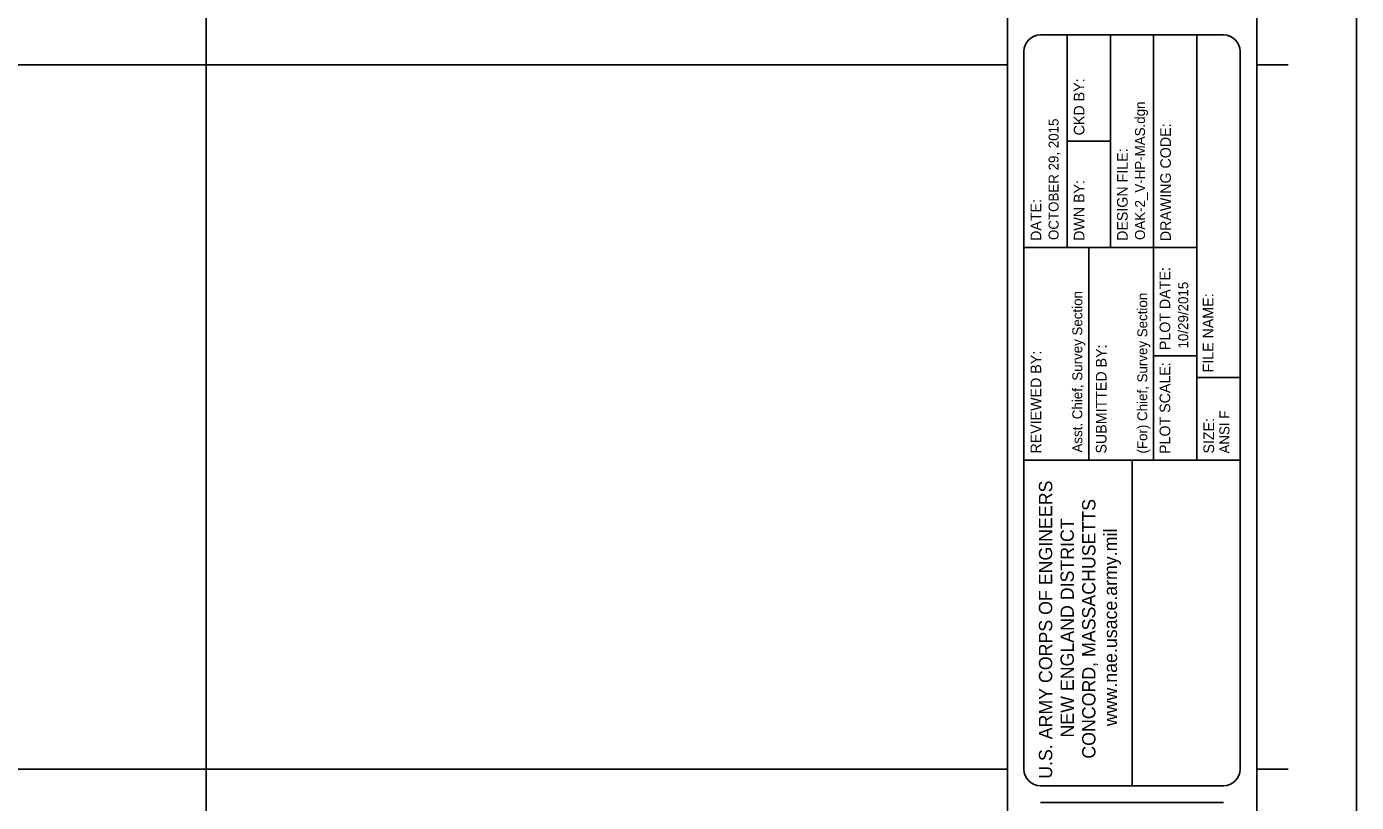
# Model space of a CAD drawing. Extents: x 0 to 3.33, y 0 to 2.33.
# Drawn here: x 2.5 to 3.333, y 0.483 to 0.97 of the extents above; entities that cross this region are included whole.
import ezdxf

# ---------------------------------------------------------------- set-up
doc = ezdxf.new("R2010")
doc.units = 0
for name, color, linetype in [('G-ANNO-NPLT', 7, 'Continuous'), ('G-ANNO-TEXT', 7, 'Continuous'), ('G-ANNO-TTLB', 7, 'Continuous'), ('G-ANNO-TTLB-GRID', 7, 'Continuous')]:
    doc.layers.add(name, color=color, linetype=linetype)

msp = doc.modelspace()

# ---------------------------------------------------------------- linework, layer by layer
at = {"layer": 'G-ANNO-NPLT'}
msp.add_lwpolyline([(0, 0), (3.33333, 0), (3.33333, 2.33333), (0, 2.33333)], close=True, dxfattribs=at)
at = {"layer": 'G-ANNO-TTLB'}
for p, q in [((3.15209, 0.83125), (3.15209, 0.96459)), ((3.17917, 0.83125), (3.17917, 0.96459)), ((3.20626, 0.69792), (3.20626, 0.96459)), ((3.23334, 0.69792), (3.23334, 0.96459)), ((3.12501, 0.50417), (3.12501, 0.95417)), ((3.29053, 0.94584), (3.27084, 0.94584)), ((3.17917, 0.89792), (3.15209, 0.89792)), ((3.15221, 0.83125), (3.12501, 0.83125)), ((3.17929, 0.83125), (3.15209, 0.83125)), ((3.16563, 0.69792), (3.16563, 0.83125)), ((3.20626, 0.83125), (3.17917, 0.83125)), ((3.23334, 0.83123), (3.20626, 0.83123)), ((3.23331, 0.76326), (3.20626, 0.76326)), ((3.26042, 0.74985), (3.23334, 0.74985)), ((3.12501, 0.69792), (3.26042, 0.69792)), ((3.19271, 0.49375), (3.19271, 0.69792)), ((3.29053, 0.50417), (3.27084, 0.50417))]:
    msp.add_line(p, q, dxfattribs=at)
for points in [[(0.12501, 0.0625), (3.11459, 0.0625), (3.11459, 2.27084), (0.12501, 2.27084)], [(3.11459, 0.0625), (3.27084, 0.0625), (3.27084, 2.27084), (3.11459, 2.27084)]]:
    msp.add_lwpolyline(points, close=True, dxfattribs=at)
for points in [[(3.25001, 0.96459), (3.13542, 0.96459)], [(3.25001, 0.96459), (3.13542, 0.96459)], [(3.25001, 0.96459), (3.13542, 0.96459)], [(3.26042, 0.50417), (3.26042, 0.95417)], [(3.25001, 0.49375), (3.13542, 0.49375)], [(3.13542, 0.48334), (3.25001, 0.48334)]]:
    msp.add_lwpolyline(points, dxfattribs=at)
for centre, start, end in [((3.13542, 0.95417), 90, 180), ((3.13542, 0.95417), 90, 180), ((3.13542, 0.95417), 90, 180), ((3.25001, 0.95417), 0, 90), ((3.25001, 0.95417), 0, 90), ((3.25001, 0.95417), 0, 90), ((3.13542, 0.50417), 180, 270), ((3.25001, 0.50417), 270, 0)]:
    msp.add_arc(centre, 0.01042, start, end, dxfattribs=at)
at = {"layer": 'G-ANNO-TTLB-GRID'}
for p, q in [((2.61251, 0.0625), (2.61251, 2.27084)), ((3.11459, 0.94584), (0.12501, 0.94584)), ((3.11459, 0.50417), (0.12501, 0.50417))]:
    msp.add_line(p, q, dxfattribs=at)

# ---------------------------------------------------------------- texts
at = {"layer": 'G-ANNO-TEXT'}
for s, height, p in [('CKD BY:', 0.006667, (3.16292, 0.90159)), ('DRAWING CODE:', 0.0066667, (3.21709, 0.83525)), ('DESIGN FILE:', 0.0066667, (3.19001, 0.83542)), ('DWN BY:', 0.006667, (3.16292, 0.83542)), ('DATE:', 0.006667, (3.13585, 0.83542)), ('PLOT DATE:', 0.006667, (3.21668, 0.76692)), ('Asst. Chief, Survey Section', 0.00625, (3.16157, 0.70271)), ('(For) Chief, Survey Section', 0.00625, (3.2023, 0.70209)), ('FILE NAME:', 0.006667, (3.24372, 0.75294)), ('SUBMITTED BY:', 0.0066667, (3.17673, 0.70209)), ('REVIEWED BY:', 0.0066667, (3.13585, 0.70209)), ('PLOT SCALE:', 0.0066667, (3.21668, 0.70185)), ('SIZE:', 0.006667, (3.24417, 0.70209))]:
    msp.add_text(s, height=height, rotation=90, dxfattribs=at).set_placement(p)
at = {"layer": 'G-ANNO-TTLB'}
for s, height, p in [('OAK-2_V-HP-MAS.dgn', 0.00625, (3.20085, 0.83595)), ('OCTOBER 29, 2015', 0.00625, (3.14669, 0.83595)), ('10/29/2015', 0.00625, (3.22791, 0.76796)), ('ANSI F', 0.00625, (3.25376, 0.70209)), ('U.S. ARMY CORPS OF ENGINEERS', 0.0083333, (3.14271, 0.49814)), ('CONCORD, MASSACHUSETTS', 0.0083333, (3.1698, 0.51076)), ('NEW ENGLAND DISTRICT', 0.0083333, (3.15626, 0.52403)), ('www.nae.usace.army.mil', 0.0083333, (3.18334, 0.53115))]:
    msp.add_text(s, height=height, rotation=90, dxfattribs=at).set_placement(p)

doc.saveas('drawing.dxf')
